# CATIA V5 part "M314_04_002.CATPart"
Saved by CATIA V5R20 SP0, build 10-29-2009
Part number: M314_04_002
Source: Unknown
Property "ARTICLENO": "M314-04-002"
Property "B": "35.000"
Property "BOMINFO": "M314-04-002"
Property "CODE": "M314-04-002"
Property "D": "5.500"
Property "FINALFORCE": "39.2 (4)"
Property "INITIALFORCE": "6.8 (0.7)"
Property "K": "10.000"
Property "L": "43.000"
Property "LINA": "M314-04-002"
Property "M": "M12x1.75"
Property "NB": "M314-04-002"
Property "NBSYN": "$CODE."
Property "NN": "M314-04"
Property "NT": "Spring Plunger"
Property "SUPPLIER": "CF"
Property "SW": "4.000"
Bounding box of the stored display mesh (mm): x -5.939 to 5.939, y 0 to 53, z -6 to 6
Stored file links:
  C:\Users\Utente\Desktop\3D files M314\M314_04_002.CATPart
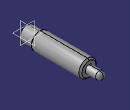
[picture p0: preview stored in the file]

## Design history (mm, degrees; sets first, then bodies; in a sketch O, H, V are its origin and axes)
Body1 "Geometry.1" (main body)
  Solid1 "M314_04_002.catpart": solid without history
